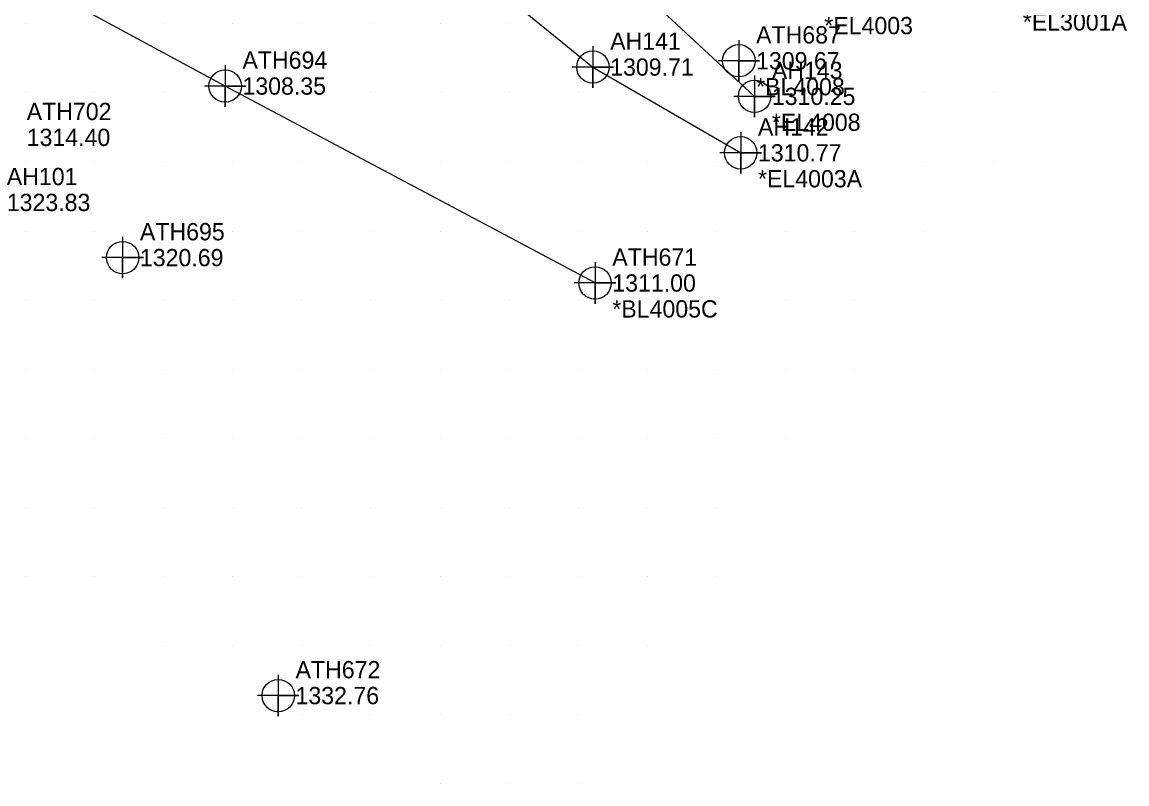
# Model space of a CAD drawing. Extents: x 1234484 to 1235382, y 695050 to 695510.
# Drawn here: x 1235159.5 to 1235319.3, y 695050 to 695160.2 of the extents above; entities that cross this region are included whole.
import ezdxf

# ---------------------------------------------------------------- set-up
doc = ezdxf.new("R2010")
doc.units = 0
for name, color, linetype in [('Exist DTM Breakline', 7, 'Continuous'), ('Exist DTM Breakline Cogo Comment', 7, 'Continuous'), ('Exist DTM Breakline Cogo Elevation', 7, 'Continuous'), ('Exist DTM Breakline Cogo Number', 7, 'Continuous'), ('Exist DTM Breakline Cogo Point CELL', 7, 'Continuous'), ('Exist DTM Breakline Underwater', 7, 'Continuous'), ('Exist DTM Drainline Cogo Comment', 7, 'Continuous'), ('Exist DTM Drainline Cogo Elevation', 7, 'Continuous'), ('Exist DTM Drainline Cogo Number', 7, 'Continuous'), ('Exist DTM Drainline Cogo Point CELL', 7, 'Continuous'), ('Exist DTM QL2 LIDAR Elevation Point', 7, 'Continuous'), ('Exist DTM Regular Point CELL', 7, 'Continuous'), ('Exist DTM Regular Point Cogo Elevation', 7, 'Continuous'), ('Exist DTM Regular Point Cogo Number', 7, 'Continuous'), ('Exist DTM Regular Point Underwater CELL', 7, 'Continuous'), ('Exist DTM Regular Point Underwater Cogo Comment', 7, 'Continuous'), ('Exist DTM Regular Point Underwater Cogo Elevation', 7, 'Continuous'), ('Exist DTM Regular Point Underwater Cogo Number', 7, 'Continuous'), ('Exist Hydro Stream or Body of Water', 7, 'Continuous'), ('Exist Roads EOP Cogo Comment', 7, 'Continuous')]:
    doc.layers.add(name, color=color, linetype=linetype)

msp = doc.modelspace()

# ---------------------------------------------------------------- linework, layer by layer
at = {"layer": 'Exist DTM Breakline'}
msp.add_lwpolyline([(1235242.403, 695122.486), (1235188.913, 695150.987), (1235163.662, 695164.651), (1235112.238, 695183.191), (1235055.183, 695204.784), (1235005.3, 695209.27), (1234956.312, 695230.116)], dxfattribs=at)
at = {"layer": 'Exist DTM Breakline Cogo Point CELL'}
for points in [[(1235188.913, 695153.987), (1235188.913, 695147.987), (1235188.913, 695150.987), (1235191.913, 695150.987), (1235185.913, 695150.987)], [(1235242.403, 695125.486), (1235242.403, 695119.486), (1235242.403, 695122.486), (1235245.403, 695122.486), (1235239.403, 695122.486)]]:
    msp.add_lwpolyline(points, dxfattribs=at)
for centre in [(1235188.913, 695150.987), (1235242.403, 695122.486)]:
    msp.add_circle(centre, 2.344, dxfattribs=at)
at = {"layer": 'Exist DTM Breakline Underwater'}
msp.add_lwpolyline([(1234948.239, 695292.841), (1234952.805, 695292.84), (1234960.83, 695292.864), (1234972.599, 695288.481), (1235023.203, 695275.502), (1235056.399, 695264.585), (1235086.587, 695258.395), (1235121.582, 695234.941), (1235168.445, 695213.485), (1235191.313, 695204.186), (1235209.05, 695188.429), (1235246.922, 695166.749), (1235265.478, 695149.496)], dxfattribs=at)
at = {"layer": 'Exist DTM Drainline Cogo Point CELL'}
for points in [[(1235242.093, 695156.734), (1235242.093, 695150.734), (1235242.093, 695153.734), (1235245.093, 695153.734), (1235239.093, 695153.734)], [(1235263.468, 695144.323), (1235263.468, 695138.323), (1235263.468, 695141.323), (1235266.468, 695141.323), (1235260.468, 695141.323)]]:
    msp.add_lwpolyline(points, dxfattribs=at)
for centre in [(1235242.093, 695153.734), (1235263.468, 695141.323)]:
    msp.add_circle(centre, 2.344, dxfattribs=at)
at = {"layer": 'Exist DTM QL2 LIDAR Elevation Point'}
for p, q in [((1235160, 695160), (1235160, 695160)), ((1235170, 695160), (1235170, 695160)), ((1235180, 695160), (1235180, 695160)), ((1235190, 695160), (1235190, 695160)), ((1235200, 695160), (1235200, 695160)), ((1235210, 695160), (1235210, 695160)), ((1235220, 695160), (1235220, 695160)), ((1235230, 695160), (1235230, 695160)), ((1235160, 695150), (1235160, 695150)), ((1235170, 695150), (1235170, 695150)), ((1235180, 695150), (1235180, 695150)), ((1235190, 695150), (1235190, 695150)), ((1235200, 695150), (1235200, 695150)), ((1235210, 695150), (1235210, 695150)), ((1235220, 695150), (1235220, 695150)), ((1235230, 695150), (1235230, 695150)), ((1235240, 695150), (1235240, 695150)), ((1235290, 695150), (1235290, 695150)), ((1235300, 695150), (1235300, 695150)), ((1235160, 695140), (1235160, 695140)), ((1235170, 695140), (1235170, 695140)), ((1235180, 695140), (1235180, 695140)), ((1235190, 695140), (1235190, 695140)), ((1235200, 695140), (1235200, 695140)), ((1235220, 695140), (1235220, 695140)), ((1235230, 695140), (1235230, 695140)), ((1235240, 695140), (1235240, 695140)), ((1235250, 695140), (1235250, 695140)), ((1235260, 695140), (1235260, 695140)), ((1235290, 695140), (1235290, 695140)), ((1235300, 695140), (1235300, 695140)), ((1235160, 695130), (1235160, 695130)), ((1235170, 695130), (1235170, 695130)), ((1235180, 695130), (1235180, 695130)), ((1235190, 695130), (1235190, 695130)), ((1235200, 695130), (1235200, 695130)), ((1235210, 695130), (1235210, 695130)), ((1235220, 695130), (1235220, 695130)), ((1235240, 695130), (1235240, 695130)), ((1235250, 695130), (1235250, 695130)), ((1235260, 695130), (1235260, 695130)), ((1235270, 695130), (1235270, 695130)), ((1235280, 695130), (1235280, 695130)), ((1235290, 695130), (1235290, 695130)), ((1235160, 695120), (1235160, 695120)), ((1235170, 695120), (1235170, 695120)), ((1235180, 695120), (1235180, 695120)), ((1235190, 695120), (1235190, 695120)), ((1235200, 695120), (1235200, 695120)), ((1235210, 695120), (1235210, 695120)), ((1235220, 695120), (1235220, 695120)), ((1235230, 695120), (1235230, 695120)), ((1235240, 695120), (1235240, 695120)), ((1235250, 695120), (1235250, 695120)), ((1235260, 695120), (1235260, 695120)), ((1235270, 695120), (1235270, 695120)), ((1235280, 695120), (1235280, 695120)), ((1235160, 695110), (1235160, 695110)), ((1235170, 695110), (1235170, 695110)), ((1235180, 695110), (1235180, 695110)), ((1235190, 695110), (1235190, 695110)), ((1235200, 695110), (1235200, 695110)), ((1235210, 695110), (1235210, 695110)), ((1235220, 695110), (1235220, 695110)), ((1235230, 695110), (1235230, 695110)), ((1235240, 695110), (1235240, 695110)), ((1235250, 695110), (1235250, 695110)), ((1235260, 695110), (1235260, 695110)), ((1235270, 695110), (1235270, 695110)), ((1235280, 695110), (1235280, 695110)), ((1235160, 695100), (1235160, 695100)), ((1235170, 695100), (1235170, 695100)), ((1235180, 695100), (1235180, 695100)), ((1235190, 695100), (1235190, 695100)), ((1235200, 695100), (1235200, 695100)), ((1235210, 695100), (1235210, 695100)), ((1235220, 695100), (1235220, 695100)), ((1235230, 695100), (1235230, 695100)), ((1235240, 695100), (1235240, 695100)), ((1235250, 695100), (1235250, 695100)), ((1235260, 695100), (1235260, 695100)), ((1235270, 695100), (1235270, 695100)), ((1235160, 695090), (1235160, 695090)), ((1235170, 695090), (1235170, 695090)), ((1235180, 695090), (1235180, 695090)), ((1235190, 695090), (1235190, 695090)), ((1235200, 695090), (1235200, 695090)), ((1235210, 695090), (1235210, 695090)), ((1235220, 695090), (1235220, 695090)), ((1235230, 695090), (1235230, 695090)), ((1235240, 695090), (1235240, 695090)), ((1235250, 695090), (1235250, 695090)), ((1235260, 695090), (1235260, 695090)), ((1235160, 695080), (1235160, 695080)), ((1235170, 695080), (1235170, 695080)), ((1235180, 695080), (1235180, 695080)), ((1235190, 695080), (1235190, 695080)), ((1235200, 695080), (1235200, 695080)), ((1235210, 695080), (1235210, 695080)), ((1235220, 695080), (1235220, 695080)), ((1235230, 695080), (1235230, 695080)), ((1235240, 695080), (1235240, 695080)), ((1235250, 695080), (1235250, 695080)), ((1235260, 695080), (1235260, 695080)), ((1235180, 695070), (1235180, 695070)), ((1235190, 695070), (1235190, 695070)), ((1235200, 695070), (1235200, 695070)), ((1235210, 695070), (1235210, 695070)), ((1235220, 695070), (1235220, 695070)), ((1235230, 695070), (1235230, 695070)), ((1235240, 695070), (1235240, 695070)), ((1235250, 695070), (1235250, 695070)), ((1235200, 695060), (1235200, 695060)), ((1235210, 695060), (1235210, 695060)), ((1235220, 695060), (1235220, 695060)), ((1235230, 695060), (1235230, 695060)), ((1235240, 695060), (1235240, 695060)), ((1235220, 695050), (1235220, 695050)), ((1235230, 695050), (1235230, 695050)), ((1235240, 695050), (1235240, 695050))]:
    msp.add_line(p, q, dxfattribs=at)
at = {"layer": 'Exist DTM Regular Point CELL'}
for points in [[(1235174.083, 695129.162), (1235174.083, 695123.162), (1235174.083, 695126.162), (1235177.083, 695126.162), (1235171.083, 695126.162)], [(1235196.589, 695065.781), (1235196.589, 695059.781), (1235196.589, 695062.781), (1235199.589, 695062.781), (1235193.589, 695062.781)]]:
    msp.add_lwpolyline(points, dxfattribs=at)
for centre in [(1235174.083, 695126.162), (1235196.589, 695062.781)]:
    msp.add_circle(centre, 2.344, dxfattribs=at)
at = {"layer": 'Exist DTM Regular Point Underwater CELL'}
for points in [[(1235263.195, 695157.644), (1235263.195, 695151.644), (1235263.195, 695154.644), (1235266.195, 695154.644), (1235260.195, 695154.644)], [(1235265.478, 695152.496), (1235265.478, 695146.496), (1235265.478, 695149.496), (1235268.478, 695149.496), (1235262.478, 695149.496)]]:
    msp.add_lwpolyline(points, dxfattribs=at)
for centre in [(1235263.195, 695154.644), (1235265.478, 695149.496)]:
    msp.add_circle(centre, 2.344, dxfattribs=at)
at = {"layer": 'Exist Hydro Stream or Body of Water'}
msp.add_lwpolyline([(1235018.754, 695261.568), (1235053.271, 695252.381), (1235081.661, 695240.144), (1235119.353, 695226.521), (1235169.371, 695199.43), (1235188.125, 695189.805), (1235205.75, 695183.352), (1235242.093, 695153.734), (1235263.468, 695141.323)], dxfattribs=at)

# ---------------------------------------------------------------- texts
at = {"layer": 'Exist DTM Breakline Cogo Comment'}
msp.add_text('*BL4005C', height=2.5, dxfattribs=at).set_placement((1235244.903, 695117.486))
at = {"layer": 'Exist DTM Breakline Cogo Elevation'}
for s, p in [('1308.35', (1235191.413, 695149.737)), ('1311.00', (1235244.903, 695121.236))]:
    msp.add_text(s, height=2.5, dxfattribs=at).set_placement(p)
at = {"layer": 'Exist DTM Breakline Cogo Number'}
for s, p in [('ATH694', (1235191.413, 695153.487)), ('ATH671', (1235244.903, 695124.986))]:
    msp.add_text(s, height=2.5, dxfattribs=at).set_placement(p)
at = {"layer": 'Exist DTM Drainline Cogo Comment'}
for s, p in [('*EL4003', (1235275.559, 695158.484)), ('*EL4003A', (1235265.968, 695136.323))]:
    msp.add_text(s, height=2.5, dxfattribs=at).set_placement(p)
at = {"layer": 'Exist DTM Drainline Cogo Elevation'}
for s, p in [('1309.71', (1235244.593, 695152.484)), ('1310.77', (1235265.968, 695140.073))]:
    msp.add_text(s, height=2.5, dxfattribs=at).set_placement(p)
at = {"layer": 'Exist DTM Drainline Cogo Number'}
for s, p in [('AH141', (1235244.593, 695156.234)), ('AH142', (1235265.968, 695143.823))]:
    msp.add_text(s, height=2.5, dxfattribs=at).set_placement(p)
at = {"layer": 'Exist DTM Regular Point Cogo Elevation'}
for s, p in [('1314.40', (1235160.209, 695142.309)), ('1323.83', (1235157.326, 695132.895)), ('1320.69', (1235176.583, 695124.912)), ('1332.76', (1235199.089, 695061.531))]:
    msp.add_text(s, height=2.5, dxfattribs=at).set_placement(p)
at = {"layer": 'Exist DTM Regular Point Cogo Number'}
for s, p in [('ATH702', (1235160.209, 695146.059)), ('AH101', (1235157.326, 695136.645)), ('ATH695', (1235176.583, 695128.662)), ('ATH672', (1235199.089, 695065.281))]:
    msp.add_text(s, height=2.5, dxfattribs=at).set_placement(p)
at = {"layer": 'Exist DTM Regular Point Underwater Cogo Comment'}
for s, p in [('*BL4008', (1235265.695, 695149.644)), ('*EL4008', (1235267.978, 695144.496))]:
    msp.add_text(s, height=2.5, dxfattribs=at).set_placement(p)
at = {"layer": 'Exist DTM Regular Point Underwater Cogo Elevation'}
for s, p in [('1309.67', (1235265.695, 695153.394)), ('1310.25', (1235267.978, 695148.246))]:
    msp.add_text(s, height=2.5, dxfattribs=at).set_placement(p)
at = {"layer": 'Exist DTM Regular Point Underwater Cogo Number'}
for s, p in [('ATH687', (1235265.695, 695157.144)), ('AH143', (1235267.978, 695151.996))]:
    msp.add_text(s, height=2.5, dxfattribs=at).set_placement(p)
at = {"layer": 'Exist Roads EOP Cogo Comment'}
msp.add_text('*EL3001A', height=2.5, dxfattribs=at).set_placement((1235304.275, 695159.014))

doc.saveas('drawing.dxf')
